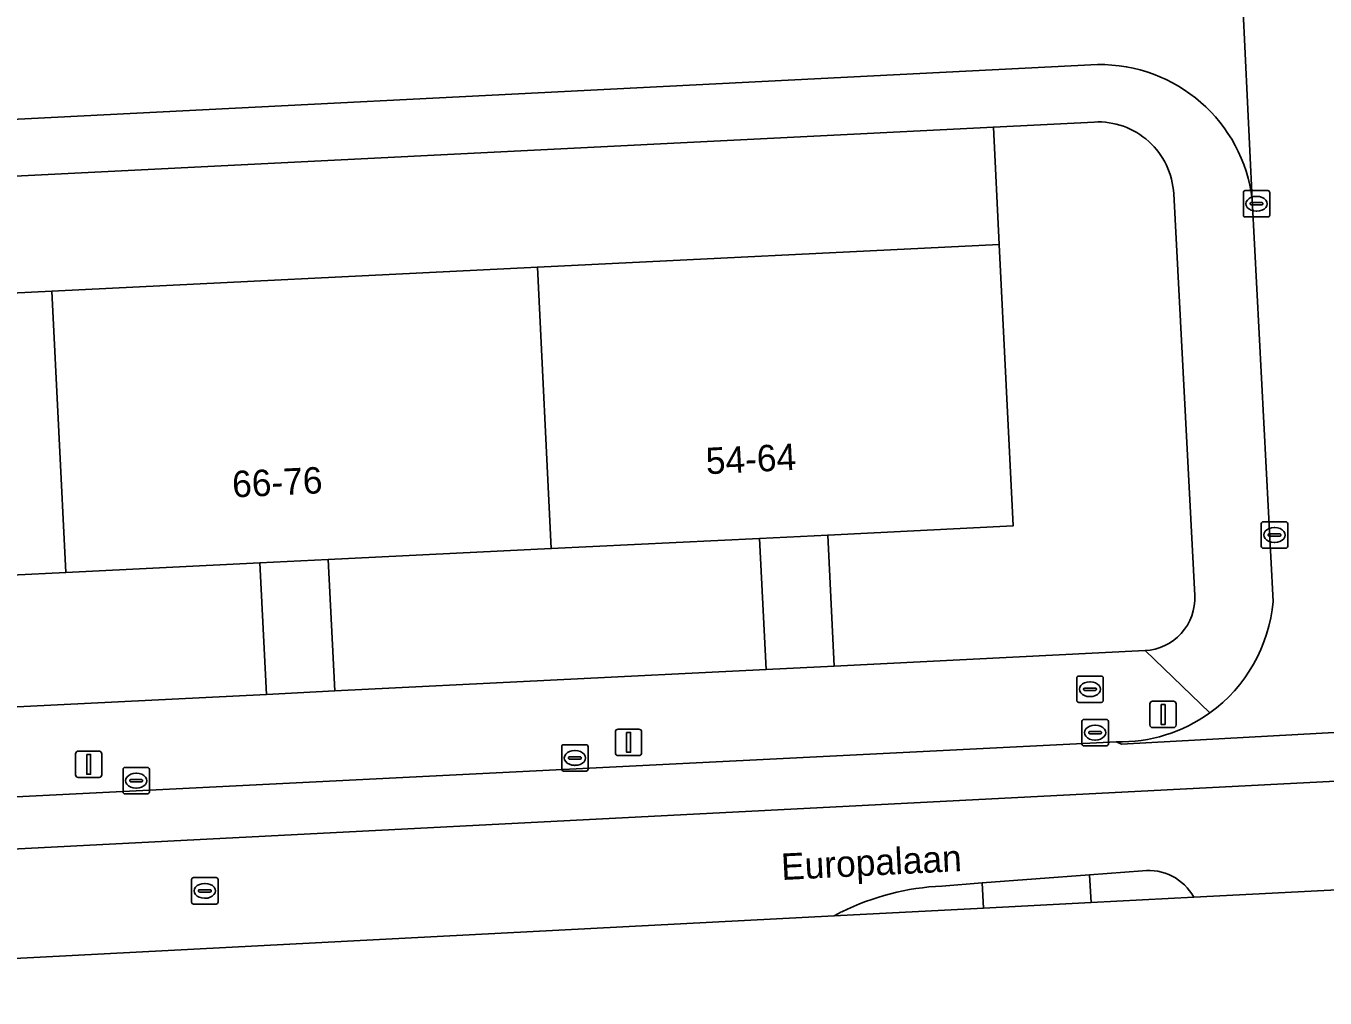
# Model space of a CAD drawing. Extents: x 161084 to 161928, y 385354 to 386522.
# Drawn here: x 161339.99 to 161389.16, y 385354.17 to 385390.94 of the extents above; entities that cross this region are included whole.
import ezdxf

# ---------------------------------------------------------------- set-up
doc = ezdxf.new("R2010")
doc.units = 0
for name, color, linetype in [('IMGEO_Berm_groen', 7, 'Continuous'), ('IMGEO_Brandkraan', 7, 'Continuous'), ('IMGEO_Groenvoorziening', 7, 'Continuous'), ('IMGEO_Kolk', 7, 'Continuous'), ('IMGEO_Lichtmast', 7, 'Continuous'), ('IMGEO_Openbare_ruimte_label', 7, 'Continuous'), ('IMGEO_Pand', 7, 'Continuous'), ('IMGEO_Pand_nummerreeks', 7, 'Continuous'), ('IMGEO_Parkeervlak_open', 7, 'Continuous'), ('IMGEO_Rijbaan_lokaal_gesloten', 7, 'Continuous'), ('IMGEO_Rijbaan_lokaal_open', 7, 'Continuous'), ('IMGEO_Rioolput', 7, 'Continuous'), ('IMGEO_Verkeerseiland_open', 7, 'Continuous'), ('IMGEO_Voetpad_open', 7, 'Continuous')]:
    doc.layers.add(name, color=color, linetype=linetype)

msp = doc.modelspace()

# ---------------------------------------------------------------- linework, layer by layer
at = {"layer": 'IMGEO_Berm_groen'}
for points in [[(161370.581, 385357.274), (161376.236, 385357.567), (161376.188, 385358.52), (161374.658, 385358.404)], [(161370.865, 385357.424), (161370.581, 385357.274)]]:
    msp.add_lwpolyline(points, dxfattribs=at)
msp.add_arc((161375.104, 385348.849), 9.565, 92.6698, 116.3037, dxfattribs=at)
at = {"layer": 'IMGEO_Brandkraan'}
for p, q in [((161379.765, 385365.423), (161379.765, 385366.275)), ((161379.84, 385366.349), (161380.692, 385366.349)), ((161380.766, 385366.275), (161380.766, 385365.423)), ((161380.024, 385365.843), (161380.024, 385365.855)), ((161380.462, 385365.806), (161380.064, 385365.806)), ((161380.067, 385365.892), (161380.465, 385365.892)), ((161380.253, 385366.129), (161380.278, 385366.129)), ((161380.508, 385365.855), (161380.508, 385365.843)), ((161380.692, 385365.349), (161379.84, 385365.349)), ((161380.276, 385365.569), (161380.251, 385365.569))]:
    msp.add_line(p, q, dxfattribs=at)
for points in [[(161379.765, 385365.423), (161379.765, 385366.275)], [(161379.84, 385366.349), (161380.692, 385366.349)], [(161380.766, 385366.275), (161380.766, 385365.423)], [(161380.692, 385365.349), (161379.84, 385365.349)]]:
    msp.add_lwpolyline(points, dxfattribs=at)
for centre, radius, start, end in [((161379.842, 385366.273), 0.0765, 91.552, 178.448), ((161379.842, 385366.273), 0.0765, 91.552, 178.448), ((161380.69, 385366.273), 0.0765, 1.552, 88.448), ((161380.69, 385366.273), 0.0765, 1.552, 88.448), ((161380.064, 385365.852), 0.0403, 85.8775, 175.7526), ((161380.061, 385365.842), 0.0366, 178.938, 274.7102), ((161380.465, 385365.849), 0.043, 264.8664, 352.4533), ((161380.469, 385365.854), 0.0386, 1.7309, 96.639), ((161379.842, 385365.425), 0.0765, 181.552, 268.448), ((161379.842, 385365.425), 0.0765, 181.552, 268.448), ((161380.69, 385365.425), 0.0765, 271.552, 358.448), ((161380.69, 385365.425), 0.0765, 271.552, 358.448)]:
    msp.add_arc(centre, radius, start, end, dxfattribs=at)
for centre, major_axis, ratio, start_param, end_param in [((161380.252, 385365.849), (-0.387, 0.002), 0.722429, 4.712389, 7.853982), ((161380.277, 385365.849), (-0.39, 0.002), 0.717154, 1.570796, 4.712389)]:
    msp.add_ellipse(centre, major_axis=major_axis, ratio=ratio, start_param=start_param, end_param=end_param, dxfattribs=at)
at = {"layer": 'IMGEO_Groenvoorziening'}
for points in [[(161380.422, 385387.307), (161376.611, 385387.114), (161376.829, 385382.675), (161377.352, 385372.028), (161370.336, 385371.683), (161370.582, 385366.726), (161382.349, 385367.312)], [(161384.229, 385369.394), (161383.434, 385384.589)]]:
    msp.add_lwpolyline(points, dxfattribs=at)
for points in [[(161368.003, 385366.597), (161367.756, 385371.556), (161359.873, 385371.169), (161351.429, 385370.754), (161351.676, 385365.783)], [(161349.09, 385365.654), (161348.843, 385370.627), (161341.494, 385370.266), (161335.311, 385369.962), (161335.558, 385364.98)]]:
    msp.add_lwpolyline(points, close=True, dxfattribs=at)
for centre, radius, start, end in [((161380.569, 385384.443), 2.868, 2.9275, 92.9469), ((161382.251, 385369.291), 1.981, 272.8472, 2.9901)]:
    msp.add_arc(centre, radius, start, end, dxfattribs=at)
at = {"layer": 'IMGEO_Kolk'}
for p, q in [((161386.069, 385383.789), (161386.069, 385384.641)), ((161386.144, 385384.715), (161386.996, 385384.715)), ((161386.557, 385384.495), (161386.582, 385384.495)), ((161387.07, 385384.641), (161387.07, 385383.789)), ((161386.328, 385384.209), (161386.328, 385384.221)), ((161386.766, 385384.172), (161386.368, 385384.172)), ((161386.371, 385384.258), (161386.769, 385384.258)), ((161386.58, 385383.935), (161386.555, 385383.935)), ((161386.812, 385384.221), (161386.812, 385384.209)), ((161386.996, 385383.715), (161386.144, 385383.715)), ((161386.749, 385371.257), (161386.749, 385372.109)), ((161386.824, 385372.183), (161387.676, 385372.183)), ((161387.75, 385372.109), (161387.75, 385371.257)), ((161387.008, 385371.677), (161387.008, 385371.689)), ((161387.446, 385371.64), (161387.048, 385371.64)), ((161387.051, 385371.726), (161387.449, 385371.726)), ((161387.237, 385371.963), (161387.262, 385371.963)), ((161387.492, 385371.689), (161387.492, 385371.677)), ((161387.676, 385371.183), (161386.824, 385371.183)), ((161387.26, 385371.403), (161387.235, 385371.403)), ((161380.033, 385364.706), (161380.885, 385364.706)), ((161379.958, 385363.78), (161379.958, 385364.632)), ((161380.217, 385364.2), (161380.217, 385364.212)), ((161380.26, 385364.249), (161380.658, 385364.249)), ((161380.446, 385364.486), (161380.471, 385364.486)), ((161380.701, 385364.212), (161380.701, 385364.2)), ((161380.959, 385364.632), (161380.959, 385363.78)), ((161360.342, 385363.75), (161361.194, 385363.75)), ((161380.655, 385364.163), (161380.257, 385364.163)), ((161380.469, 385363.926), (161380.444, 385363.926)), ((161360.267, 385362.824), (161360.267, 385363.676)), ((161360.526, 385363.244), (161360.526, 385363.256)), ((161360.569, 385363.293), (161360.967, 385363.293)), ((161360.755, 385363.53), (161360.78, 385363.53)), ((161361.01, 385363.256), (161361.01, 385363.244)), ((161361.268, 385363.676), (161361.268, 385362.824)), ((161380.885, 385363.706), (161380.033, 385363.706)), ((161343.662, 385361.964), (161343.662, 385362.816)), ((161343.737, 385362.89), (161344.589, 385362.89)), ((161344.663, 385362.816), (161344.663, 385361.964)), ((161361.194, 385362.75), (161360.342, 385362.75)), ((161360.964, 385363.207), (161360.566, 385363.207)), ((161360.778, 385362.97), (161360.753, 385362.97)), ((161343.921, 385362.384), (161343.921, 385362.396)), ((161344.359, 385362.347), (161343.961, 385362.347)), ((161343.964, 385362.433), (161344.362, 385362.433)), ((161344.15, 385362.67), (161344.175, 385362.67)), ((161344.405, 385362.396), (161344.405, 385362.384)), ((161344.589, 385361.89), (161343.737, 385361.89)), ((161344.173, 385362.11), (161344.148, 385362.11))]:
    msp.add_line(p, q, dxfattribs=at)
for points in [[(161386.069, 385383.789), (161386.069, 385384.641)], [(161386.144, 385384.715), (161386.996, 385384.715)], [(161387.07, 385384.641), (161387.07, 385383.789)], [(161386.996, 385383.715), (161386.144, 385383.715)], [(161386.749, 385371.257), (161386.749, 385372.109)], [(161386.824, 385372.183), (161387.676, 385372.183)], [(161387.75, 385372.109), (161387.75, 385371.257)], [(161387.676, 385371.183), (161386.824, 385371.183)], [(161380.033, 385364.706), (161380.885, 385364.706)], [(161379.958, 385363.78), (161379.958, 385364.632)], [(161380.959, 385364.632), (161380.959, 385363.78)], [(161360.342, 385363.75), (161361.194, 385363.75)], [(161360.267, 385362.824), (161360.267, 385363.676)], [(161361.268, 385363.676), (161361.268, 385362.824)], [(161380.885, 385363.706), (161380.033, 385363.706)], [(161343.662, 385361.964), (161343.662, 385362.816)], [(161343.737, 385362.89), (161344.589, 385362.89)], [(161344.663, 385362.816), (161344.663, 385361.964)], [(161361.194, 385362.75), (161360.342, 385362.75)], [(161344.589, 385361.89), (161343.737, 385361.89)]]:
    msp.add_lwpolyline(points, dxfattribs=at)
for centre, radius, start, end in [((161386.146, 385384.639), 0.0765, 91.552, 178.448), ((161386.146, 385384.639), 0.0765, 91.552, 178.448), ((161386.994, 385384.639), 0.0765, 1.552, 88.448), ((161386.994, 385384.639), 0.0765, 1.552, 88.448), ((161386.368, 385384.218), 0.0403, 85.8775, 175.7526), ((161386.365, 385384.208), 0.0366, 178.938, 274.7102), ((161386.769, 385384.215), 0.043, 264.8664, 352.4533), ((161386.773, 385384.22), 0.0386, 1.7309, 96.639), ((161386.146, 385383.791), 0.0765, 181.552, 268.448), ((161386.146, 385383.791), 0.0765, 181.552, 268.448), ((161386.994, 385383.791), 0.0765, 271.552, 358.448), ((161386.994, 385383.791), 0.0765, 271.552, 358.448), ((161386.826, 385372.107), 0.0765, 91.552, 178.448), ((161386.826, 385372.107), 0.0765, 91.552, 178.448), ((161387.674, 385372.107), 0.0765, 1.552, 88.448), ((161387.674, 385372.107), 0.0765, 1.552, 88.448), ((161387.048, 385371.686), 0.0403, 85.8775, 175.7526), ((161387.045, 385371.676), 0.0366, 178.938, 274.7102), ((161387.449, 385371.683), 0.043, 264.8664, 352.4533), ((161387.453, 385371.688), 0.0386, 1.7309, 96.639), ((161386.826, 385371.259), 0.0765, 181.552, 268.448), ((161386.826, 385371.259), 0.0765, 181.552, 268.448), ((161387.674, 385371.259), 0.0765, 271.552, 358.448), ((161387.674, 385371.259), 0.0765, 271.552, 358.448), ((161380.035, 385364.63), 0.0765, 91.552, 178.448), ((161380.035, 385364.63), 0.0765, 91.552, 178.448), ((161380.883, 385364.63), 0.0765, 1.552, 88.448), ((161380.883, 385364.63), 0.0765, 1.552, 88.448), ((161380.257, 385364.209), 0.0403, 85.8775, 175.7526), ((161380.662, 385364.211), 0.0386, 1.7309, 96.639), ((161360.344, 385363.674), 0.0765, 91.552, 178.448), ((161360.344, 385363.674), 0.0765, 91.552, 178.448), ((161361.192, 385363.674), 0.0765, 1.552, 88.448), ((161361.192, 385363.674), 0.0765, 1.552, 88.448), ((161380.035, 385363.782), 0.0765, 181.552, 268.448), ((161380.035, 385363.782), 0.0765, 181.552, 268.448), ((161380.254, 385364.199), 0.0366, 178.938, 274.7102), ((161380.658, 385364.206), 0.043, 264.8664, 352.4533), ((161380.883, 385363.782), 0.0765, 271.552, 358.448), ((161380.883, 385363.782), 0.0765, 271.552, 358.448), ((161360.566, 385363.253), 0.0403, 85.8775, 175.7526), ((161360.563, 385363.243), 0.0366, 178.938, 274.7102), ((161360.967, 385363.25), 0.043, 264.8664, 352.4533), ((161360.971, 385363.255), 0.0386, 1.7309, 96.639), ((161343.739, 385362.814), 0.0765, 91.552, 178.448), ((161343.739, 385362.814), 0.0765, 91.552, 178.448), ((161344.587, 385362.814), 0.0765, 1.552, 88.448), ((161344.587, 385362.814), 0.0765, 1.552, 88.448), ((161360.344, 385362.826), 0.0765, 181.552, 268.448), ((161360.344, 385362.826), 0.0765, 181.552, 268.448), ((161361.192, 385362.826), 0.0765, 271.552, 358.448), ((161361.192, 385362.826), 0.0765, 271.552, 358.448), ((161343.961, 385362.393), 0.0403, 85.8775, 175.7526), ((161343.958, 385362.383), 0.0366, 178.938, 274.7102), ((161344.362, 385362.39), 0.043, 264.8664, 352.4533), ((161344.366, 385362.395), 0.0386, 1.7309, 96.639), ((161343.739, 385361.966), 0.0765, 181.552, 268.448), ((161343.739, 385361.966), 0.0765, 181.552, 268.448), ((161344.587, 385361.966), 0.0765, 271.552, 358.448), ((161344.587, 385361.966), 0.0765, 271.552, 358.448)]:
    msp.add_arc(centre, radius, start, end, dxfattribs=at)
for centre, major_axis, ratio, start_param, end_param in [((161386.556, 385384.215), (-0.387, 0.002), 0.722429, 4.712389, 7.853982), ((161386.581, 385384.215), (-0.39, 0.002), 0.717154, 1.570796, 4.712389), ((161387.236, 385371.683), (-0.387, 0.002), 0.722429, 4.712389, 7.853982), ((161387.261, 385371.683), (-0.39, 0.002), 0.717154, 1.570796, 4.712389), ((161380.445, 385364.206), (-0.387, 0.002), 0.722429, 4.712389, 7.853982), ((161380.47, 385364.206), (-0.39, 0.002), 0.717154, 1.570796, 4.712389), ((161360.754, 385363.25), (-0.387, 0.002), 0.722429, 4.712389, 7.853982), ((161360.779, 385363.25), (-0.39, 0.002), 0.717154, 1.570796, 4.712389), ((161344.149, 385362.39), (-0.387, 0.002), 0.722429, 4.712389, 7.853982), ((161344.174, 385362.39), (-0.39, 0.002), 0.717154, 1.570796, 4.712389)]:
    msp.add_ellipse(centre, major_axis=major_axis, ratio=ratio, start_param=start_param, end_param=end_param, dxfattribs=at)
at = {"layer": 'IMGEO_Lichtmast'}
for p, q in [((161382.534, 385364.496), (161382.534, 385365.296)), ((161382.534, 385365.296), (161382.534, 385364.496)), ((161382.634, 385365.396), (161383.424, 385365.396)), ((161383.424, 385365.396), (161382.634, 385365.396)), ((161383.524, 385365.296), (161383.524, 385364.496)), ((161383.524, 385364.496), (161383.524, 385365.296)), ((161362.302, 385363.438), (161362.302, 385364.238)), ((161362.302, 385364.238), (161362.302, 385363.438)), ((161362.402, 385364.338), (161363.192, 385364.338)), ((161363.192, 385364.338), (161362.402, 385364.338)), ((161363.292, 385364.238), (161363.292, 385363.438)), ((161363.292, 385363.438), (161363.292, 385364.238)), ((161383.424, 385364.396), (161382.634, 385364.396)), ((161382.634, 385364.396), (161383.424, 385364.396)), ((161341.867, 385362.609), (161341.867, 385363.409)), ((161341.867, 385363.409), (161341.867, 385362.609)), ((161341.967, 385363.509), (161342.757, 385363.509)), ((161342.757, 385363.509), (161341.967, 385363.509)), ((161342.857, 385363.409), (161342.857, 385362.609)), ((161342.857, 385362.609), (161342.857, 385363.409)), ((161363.192, 385363.338), (161362.402, 385363.338)), ((161362.402, 385363.338), (161363.192, 385363.338)), ((161342.757, 385362.509), (161341.967, 385362.509)), ((161341.967, 385362.509), (161342.757, 385362.509))]:
    msp.add_line(p, q, dxfattribs=at)
for points in [[(161382.954, 385365.271), (161383.104, 385365.271), (161383.104, 385364.521), (161382.954, 385364.521), (161382.954, 385365.271)], [(161362.722, 385364.213), (161362.872, 385364.213), (161362.872, 385363.463), (161362.722, 385363.463), (161362.722, 385364.213)], [(161342.287, 385363.384), (161342.437, 385363.384), (161342.437, 385362.634), (161342.287, 385362.634), (161342.287, 385363.384)]]:
    msp.add_lwpolyline(points, dxfattribs=at)
for centre, start, end in [((161382.634, 385365.296), 90, 180), ((161382.634, 385365.296), 90, 180), ((161383.424, 385365.296), 0, 90), ((161383.424, 385365.296), 360, 90), ((161362.402, 385364.238), 90, 180), ((161362.402, 385364.238), 90, 180), ((161363.192, 385364.238), 0, 90), ((161363.192, 385364.238), 360, 90), ((161382.634, 385364.496), 180, 270), ((161382.634, 385364.496), 180, 270), ((161383.424, 385364.496), 270, 0), ((161383.424, 385364.496), 270, 0), ((161341.967, 385363.409), 90, 180), ((161341.967, 385363.409), 90, 180), ((161342.757, 385363.409), 0, 90), ((161342.757, 385363.409), 360, 90), ((161362.402, 385363.438), 180, 270), ((161362.402, 385363.438), 180, 270), ((161363.192, 385363.438), 270, 0), ((161363.192, 385363.438), 270, 0), ((161341.967, 385362.609), 180, 270), ((161341.967, 385362.609), 180, 270), ((161342.757, 385362.609), 270, 0), ((161342.757, 385362.609), 270, 0)]:
    msp.add_arc(centre, 0.1, start, end, dxfattribs=at)
at = {"layer": 'IMGEO_Pand'}
for points in [[(161367.756, 385371.556), (161370.336, 385371.683), (161377.352, 385372.028), (161376.829, 385382.675), (161359.35, 385381.816), (161359.873, 385371.169)], [(161348.843, 385370.627), (161351.429, 385370.754), (161359.873, 385371.169), (161359.35, 385381.816), (161340.971, 385380.913), (161341.494, 385370.266)], [(161332.659, 385369.832), (161335.311, 385369.962), (161341.494, 385370.266), (161340.971, 385380.913), (161323.492, 385380.054), (161324.015, 385369.407)]]:
    msp.add_lwpolyline(points, close=True, dxfattribs=at)
at = {"layer": 'IMGEO_Parkeervlak_open'}
msp.add_lwpolyline([(161305.797, 385383.566), (161306.013, 385379.195), (161323.492, 385380.054), (161340.971, 385380.913), (161359.35, 385381.816), (161376.829, 385382.675), (161376.611, 385387.114)], close=True, dxfattribs=at)
at = {"layer": 'IMGEO_Rijbaan_lokaal_gesloten'}
for points in [[(161508.768, 385368.474), (161604.686, 385373.29), (161611.842, 385373.703), (161615.993, 385374.116), (161622.181, 385375.572), (161612.776, 385375.763), (161606.577, 385375.444), (161537.172, 385371.897), (161505.307, 385370.314), (161500.052, 385370.04), (161436.355, 385366.757), (161401.799, 385364.905), (161400.42, 385364.894), (161400.333, 385364.8), (161381.454, 385363.768), (161381.262, 385363.858), (161323.951, 385361)], [(161292.857, 385361.465), (161286.612, 385360.011), (161288.172, 385359.529), (161291.222, 385358.909), (161294.158, 385358.451), (161297.736, 385358.198), (161302.025, 385358.107), (161303.986, 385358.072), (161307.966, 385358.21), (161314.892, 385358.542), (161402.097, 385363.009), (161508.768, 385368.474)], [(161402.333, 385358.921), (161402.264, 385360.078), (161402.097, 385363.009), (161314.892, 385358.542), (161307.966, 385358.21), (161303.986, 385358.072), (161302.025, 385358.107), (161297.736, 385358.198), (161294.158, 385358.451), (161291.222, 385358.909), (161288.172, 385359.529), (161286.612, 385360.011), (161286.602, 385360.009)], [(161374.658, 385358.404), (161376.188, 385358.52), (161380.244, 385358.826), (161382.253, 385358.978)], [(161384.19, 385357.98), (161391.347, 385358.351), (161402.333, 385358.921)], [(161252.414, 385356.596), (161252.644, 385354.672), (161310.703, 385354.168), (161370.581, 385357.274), (161370.865, 385357.424)]]:
    msp.add_lwpolyline(points, dxfattribs=at)
for centre, radius, start, end in [((161382.49, 385357.058), 1.935, 28.4605, 97.024), ((161375.104, 385348.849), 9.565, 92.6698, 116.3037)]:
    msp.add_arc(centre, radius, start, end, dxfattribs=at)
at = {"layer": 'IMGEO_Rijbaan_lokaal_open'}
for points in [[(161383.849, 385435.924), (161385.609, 385400.952), (161386.409, 385384.373), (161387.194, 385369.169)], [(161386.409, 385384.373), (161385.609, 385400.952)], [(161325.742, 385386.712), (161380.544, 385389.48)], [(161381.262, 385363.858), (161381.454, 385363.768), (161400.333, 385364.8), (161400.42, 385364.894)]]:
    msp.add_lwpolyline(points, dxfattribs=at)
for centre, radius, start, end in [((161380.635, 385383.663), 5.818, 7.0121, 90.8919), ((161381.395, 385369.676), 5.821, 305.7858, 355.003), ((161381.398, 385369.673), 5.816, 268.6555, 305.7775)]:
    msp.add_arc(centre, radius, start, end, dxfattribs=at)
at = {"layer": 'IMGEO_Rioolput'}
for p, q in [((161346.257, 385357.795), (161346.257, 385358.647)), ((161346.332, 385358.721), (161347.184, 385358.721)), ((161346.745, 385358.501), (161346.77, 385358.501)), ((161347.258, 385358.647), (161347.258, 385357.795)), ((161346.516, 385358.215), (161346.516, 385358.227)), ((161346.954, 385358.178), (161346.556, 385358.178)), ((161346.559, 385358.264), (161346.957, 385358.264)), ((161346.768, 385357.941), (161346.743, 385357.941)), ((161347, 385358.227), (161347, 385358.215)), ((161347.184, 385357.721), (161346.332, 385357.721))]:
    msp.add_line(p, q, dxfattribs=at)
for points in [[(161346.257, 385357.795), (161346.257, 385358.647)], [(161346.332, 385358.721), (161347.184, 385358.721)], [(161347.258, 385358.647), (161347.258, 385357.795)], [(161347.184, 385357.721), (161346.332, 385357.721)]]:
    msp.add_lwpolyline(points, dxfattribs=at)
for centre, radius, start, end in [((161346.334, 385358.645), 0.0765, 91.552, 178.448), ((161346.334, 385358.645), 0.0765, 91.552, 178.448), ((161347.182, 385358.645), 0.0765, 1.552, 88.448), ((161347.182, 385358.645), 0.0765, 1.552, 88.448), ((161346.556, 385358.224), 0.0403, 85.8775, 175.7526), ((161346.553, 385358.214), 0.0366, 178.938, 274.7102), ((161346.957, 385358.221), 0.043, 264.8664, 352.4533), ((161346.961, 385358.226), 0.0386, 1.7309, 96.639), ((161346.334, 385357.797), 0.0765, 181.552, 268.448), ((161346.334, 385357.797), 0.0765, 181.552, 268.448), ((161347.182, 385357.797), 0.0765, 271.552, 358.448), ((161347.182, 385357.797), 0.0765, 271.552, 358.448)]:
    msp.add_arc(centre, radius, start, end, dxfattribs=at)
for centre, major_axis, ratio, start_param, end_param in [((161346.744, 385358.221), (-0.387, 0.002), 0.722429, 4.712389, 7.853982), ((161346.769, 385358.221), (-0.39, 0.002), 0.717154, 1.570796, 4.712389)]:
    msp.add_ellipse(centre, major_axis=major_axis, ratio=ratio, start_param=start_param, end_param=end_param, dxfattribs=at)
at = {"layer": 'IMGEO_Verkeerseiland_open'}
for points in [[(161382.253, 385358.978), (161380.244, 385358.826), (161380.309, 385357.778)], [(161380.309, 385357.778), (161384.19, 385357.98)]]:
    msp.add_lwpolyline(points, dxfattribs=at)
msp.add_arc((161382.49, 385357.058), 1.935, 28.4605, 97.024, dxfattribs=at)
at = {"layer": 'IMGEO_Voetpad_open'}
for points in [[(161380.544, 385389.48), (161325.742, 385386.712)], [(161267.203, 385378.413), (161273.677, 385379.254), (161297.043, 385382.22), (161305.585, 385383.564), (161305.797, 385383.566), (161376.611, 385387.114)], [(161376.611, 385387.114), (161380.422, 385387.307)], [(161383.434, 385384.589), (161384.229, 385369.394)], [(161387.194, 385369.169), (161386.409, 385384.373)], [(161384.799, 385364.954), (161382.349, 385367.312), (161370.582, 385366.726), (161368.003, 385366.597), (161351.676, 385365.783), (161349.09, 385365.654), (161335.558, 385364.98), (161332.906, 385364.848), (161316.602, 385364.035), (161313.733, 385363.892), (161306.74, 385363.544)], [(161382.349, 385367.312), (161384.799, 385364.954)], [(161323.951, 385361), (161381.262, 385363.858)]]:
    msp.add_lwpolyline(points, dxfattribs=at)
for points in [[(161370.582, 385366.726), (161370.336, 385371.683), (161367.756, 385371.556), (161368.003, 385366.597)], [(161351.676, 385365.783), (161351.429, 385370.754), (161348.843, 385370.627), (161349.09, 385365.654)], [(161376.236, 385357.567), (161380.309, 385357.778), (161380.244, 385358.826), (161376.188, 385358.52)]]:
    msp.add_lwpolyline(points, close=True, dxfattribs=at)
for centre, radius, start, end in [((161380.635, 385383.663), 5.818, 7.0121, 90.8919), ((161380.569, 385384.443), 2.868, 2.9275, 92.9469), ((161382.251, 385369.291), 1.981, 272.8472, 2.9901), ((161381.395, 385369.676), 5.821, 305.7858, 355.003), ((161381.398, 385369.673), 5.816, 268.6555, 305.7775)]:
    msp.add_arc(centre, radius, start, end, dxfattribs=at)

# ---------------------------------------------------------------- texts
at = {"layer": 'IMGEO_Openbare_ruimte_label'}
msp.add_text('Europalaan', height=1, rotation=2.8653, dxfattribs=at).set_placement((161368.597, 385358.63))
at = {"layer": 'IMGEO_Pand_nummerreeks'}
for s, rotation, p in [('54-64', 2.8142, (161365.746, 385373.981)), ('66-76', 2.8126, (161347.817, 385373.1))]:
    msp.add_text(s, height=1, rotation=rotation, dxfattribs=at).set_placement(p)

doc.saveas('drawing.dxf')
